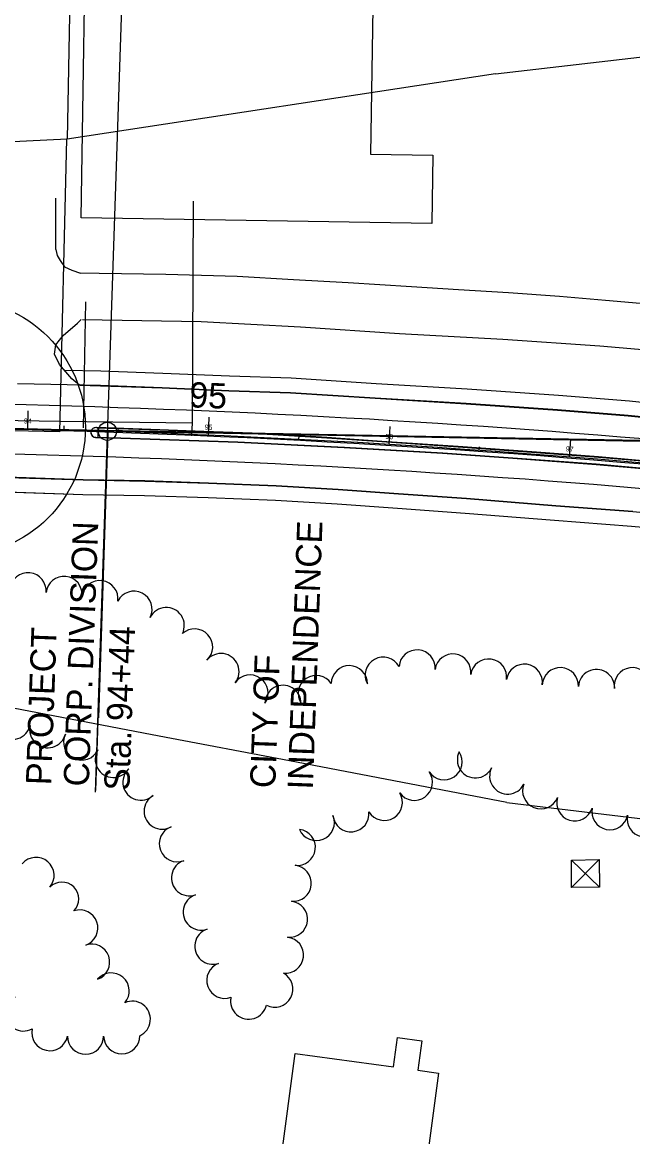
# Model space of a CAD drawing. Extents: x -25029 to 2274964, y -81170 to 687028.
# Drawn here: x -7558 to -7220, y -66444 to -65828 of the extents above; entities that cross this region are included whole.
import ezdxf

# ---------------------------------------------------------------- set-up
doc = ezdxf.new("R2010")
doc.units = 0
for name, color, linetype in [('81911BEA - RW_X_Fee_RW', 7, 'Continuous'), ('AP_X_Lights', 7, 'Continuous'), ('AP_X_Markings', 7, 'Continuous'), ('BD_X_Canopy', 7, 'Continuous'), ('BLDG', 7, 'Continuous'), ('DV_X_Corp_Line', 7, 'Continuous'), ('GE_X_CL_100', 7, 'Continuous'), ('GE_X_CL_20', 7, 'Continuous'), ('GK_Visualization', 7, 'Continuous'), ('MT_P_Edge_Line', 7, 'Continuous'), ('MT_P_Lane_Line', 7, 'Continuous'), ('PM_P_Stop_Line', 7, 'Continuous'), ('PV_X_EOP', 7, 'Continuous'), ('TRANSPWRLN', 7, 'Continuous'), ('TREES', 7, 'Continuous')]:
    doc.layers.add(name, color=color, linetype=linetype)

msp = doc.modelspace()

# ---------------------------------------------------------------- linework, layer by layer
at = {"layer": '81911BEA - RW_X_Fee_RW'}
msp.add_line((-7296.2, -65856.19), (-7533.08, -65892.28), dxfattribs=at)
for points in [[(-7296.2, -65856.19), (-7146.45, -65838.75), (-7145.25, -65838.61)], [(-7533.08, -65892.28), (-7660.66, -65898.53), (-7677.81, -65899.37)], [(-7289.97, -66259.31), (-7410.13, -66236.33), (-7482.13, -66222.56), (-7598.71, -66200.26), (-7782.14, -66167.64)], [(-7289.97, -66259.31), (-7139.67, -66277.34), (-7138.07, -66277.53)]]:
    msp.add_lwpolyline(points, dxfattribs=at)
at = {"layer": 'AP_X_Lights'}
msp.add_lwpolyline([(-7600.57, -66086.28), (-7524.38, -66088.82), (-7490.24, -66089.44), (-7455.15, -66090.65), (-7417.9, -66092.11), (-7383.77, -66094.13), (-7350.34, -66096.49), (-7312.85, -66099.14), (-7263.47, -66103.16), (-7220.94, -66106.34), (-7175.12, -66110.42), (-7125.17, -66115.15), (-7081.28, -66119.12), (-7044.93, -66123.63), (-7002.82, -66128.55), (-6956.8, -66134.1), (-6913.64, -66139.8), (-6870.76, -66146.32)], dxfattribs=at)
at = {"layer": 'AP_X_Markings'}
for p, q in [((-7464.12, -66056.51), (-7463.82, -66049.29)), ((-7510.49, -66054.77), (-7515.79, -66212.53))]:
    msp.add_line(p, q, dxfattribs=at)
at = {"layer": 'BD_X_Canopy'}
for p, q in [((-7463.82, -66049.29), (-7463.15, -65926.63)), ((-7523.97, -66052.08), (-7522.66, -65982.31)), ((-7751.13, -66045.45), (-7537.16, -66048.31)), ((-7537.16, -66048.31), (-7463.82, -66049.29)), ((-7594, -66051.77), (-7120.12, -66060.66)), ((-7534.79, -66052.88), (-7534.76, -66050.88))]:
    msp.add_line(p, q, dxfattribs=at)
msp.add_circle((-7594, -66051.77), 71.03, dxfattribs=at)
at = {"layer": 'BLDG'}
for points in [[(-7362.65, -65738.59), (-7365.24, -65900.65), (-7330.85, -65901.2), (-7331.45, -65938.87), (-7525.36, -65935.77), (-7522.16, -65736.04)], [(-7352.52, -66405.54), (-7350.36, -66389.41), (-7336.89, -66391.21), (-7339.08, -66407.55), (-7327.63, -66409.08), (-7343.54, -66528.02), (-7422.86, -66517.41), (-7406.92, -66398.26)]]:
    msp.add_lwpolyline(points, close=True, dxfattribs=at)
at = {"layer": 'DV_X_Corp_Line'}
for p, q in [((-7501.07, -65763.18), (-7517.55, -66253.54)), ((-7531.46, -65806.7), (-7533.08, -65892.28)), ((-7533.48, -65892.3), (-7537.3, -66054.17)), ((-7533.08, -65892.28), (-7533.48, -65892.3)), ((-7533.08, -65892.28), (-7533.48, -65892.3)), ((-7533.48, -65892.3), (-7533.08, -65892.28)), ((-7533.48, -65892.3), (-7533.08, -65892.28)), ((-7537.3, -66054.17), (-7737.3, -66050.39))]:
    msp.add_line(p, q, dxfattribs=at)
at = {"layer": 'GE_X_CL_100'}
for p, q in [((-7554.82, -66052.64), (-7554.57, -66042.64)), ((-7454.88, -66056.07), (-7454.45, -66046.08)), ((-7510.84, -66053.93), (-7517.46, -66252.67)), ((-7510.84, -66053.93), (-7510.84, -66053.93)), ((-7355.02, -66061.24), (-7354.41, -66051.26)), ((-7255.26, -66068.15), (-7254.48, -66058.19))]:
    msp.add_line(p, q, dxfattribs=at)
msp.add_circle((-7510.84, -66053.93), 5, dxfattribs=at)
msp.add_arc((-7701.63, -71785.78), 5735.02, 79.475877, 88.9247, dxfattribs=at)
at = {"layer": 'GE_X_CL_20'}
for p, q in [((-12238.95, -65963.84), (-7122.08, -66061.19)), ((-7554.82, -66052.64), (-7554.77, -66050.64)), ((-7504.85, -66054.13), (-7504.78, -66052.14)), ((-7454.88, -66056.07), (-7454.8, -66054.07)), ((-7404.94, -66058.44), (-7404.84, -66056.44)), ((-7355.02, -66061.24), (-7354.9, -66059.24)), ((-7305.12, -66064.48), (-7304.99, -66062.49)), ((-7255.26, -66068.15), (-7255.1, -66066.16))]:
    msp.add_line(p, q, dxfattribs=at)
msp.add_arc((-7704.96, -71780.77), 5729.63, 79.452222, 88.91, dxfattribs=at)
at = {"layer": 'GK_Visualization'}
msp.add_arc((-7701.63, -71785.78), 5735.02, 79.475877, 88.9247, dxfattribs=at)
msp.add_arc((-7701.63, -71785.78), 5735.02, 79.475877, 88.9247, dxfattribs=at)
at = {"layer": 'MT_P_Edge_Line'}
for p, q in [((-7514.65, -66028.91), (-7525.98, -66028.67)), ((-7480.51, -66030.09), (-7514.65, -66028.91)), ((-7443.6, -66031.69), (-7480.52, -66030.09)), ((-7409.6, -66032.8), (-7443.59, -66031.69)), ((-7362.71, -66035.86), (-7409.61, -66032.8)), ((-7312.44, -66038.85), (-7362.71, -66035.86)), ((-7261.91, -66042.33), (-7312.44, -66038.85)), ((-7222.85, -66045.51), (-7261.91, -66042.33)), ((-7188.08, -66048.95), (-7222.86, -66045.51)), ((-7516.74, -66051.68), (-7481.89, -66052.87)), ((-7481.88, -66052.87), (-7457.47, -66053.86)), ((-7457.48, -66053.86), (-7425.38, -66055.01)), ((-7425.37, -66055.02), (-7389.51, -66057.22)), ((-7503.41, -66057.9), (-7517.33, -66057.51)), ((-7438.71, -66060.13), (-7503.41, -66057.9)), ((-7379.78, -66063.16), (-7438.72, -66060.13)), ((-7389.51, -66057.22), (-7358.97, -66059.31)), ((-7358.97, -66059.31), (-7316.75, -66062.21)), ((-7325.39, -66066.23), (-7379.78, -66063.16)), ((-7286.6, -66068.98), (-7325.39, -66066.23)), ((-7316.75, -66062.21), (-7273.56, -66065.33)), ((-7273.56, -66065.33), (-7239.11, -66067.92)), ((-7239.1, -66067.92), (-7202.49, -66071.19)), ((-7240.41, -66072.44), (-7286.6, -66068.98)), ((-7204.86, -66075.62), (-7240.42, -66072.44)), ((-7600.34, -66078.03), (-7524.17, -66080.57)), ((-7524.17, -66080.57), (-7490.03, -66081.19)), ((-7490.03, -66081.19), (-7454.85, -66082.4)), ((-7454.84, -66082.4), (-7417.49, -66083.86)), ((-7417.49, -66083.87), (-7383.24, -66085.9)), ((-7383.24, -66085.9), (-7349.76, -66088.27)), ((-7349.76, -66088.27), (-7312.23, -66090.92)), ((-7312.22, -66090.92), (-7262.82, -66094.94)), ((-7262.83, -66094.94), (-7220.27, -66098.12))]:
    msp.add_line(p, q, dxfattribs=at)
msp.add_lwpolyline([(-7515.97, -66057.26), (-7515.88, -66051.96), (-7516.98, -66051.9), (-7517.81, -66051.95), (-7518.32, -66052.11), (-7518.79, -66052.38), (-7519.19, -66052.72), (-7519.48, -66053.09), (-7519.72, -66053.53), (-7519.85, -66053.92), (-7519.93, -66054.41), (-7519.89, -66055.03), (-7519.75, -66055.55), (-7519.48, -66056.07), (-7519.07, -66056.55), (-7518.66, -66056.86), (-7518.12, -66057.12), (-7517.54, -66057.25), (-7516.94, -66057.28), (-7516.21, -66057.3)], close=True, dxfattribs=at)
at = {"layer": 'MT_P_Lane_Line'}
for radius, start in [(5748.29, 80.845144), (5720.86, 80.84919)]:
    msp.add_arc((-7701.63, -71785.78), radius, start, 88.9247, dxfattribs=at)
at = {"layer": 'PM_P_Stop_Line'}
msp.add_line((-12236.92, -65964.61), (-7120.03, -66060.65), dxfattribs=at)
msp.add_arc((-7701.44, -71780.38), 5729.63, 79.466922, 88.9247, dxfattribs=at)
at = {"layer": 'PV_X_EOP'}
for p, q in [((-7539.35, -65953.27), (-7539.35, -65924.97)), ((-7539.35, -65953.27), (-7538.68, -65956.62)), ((-7538.68, -65956.62), (-7537.01, -65959.47)), ((-7537.01, -65959.47), (-7534.5, -65962.82)), ((-7534.5, -65962.82), (-7530.48, -65964.83)), ((-7530.48, -65964.83), (-7525.63, -65966.39)), ((-7524.63, -65992.11), (-7458.97, -65993.19)), ((-7458.97, -65993.19), (-7403.95, -65996.13)), ((-7403.95, -65996.13), (-7349.22, -65999.84)), ((-7349.22, -65999.84), (-7292.17, -66003.03)), ((-7292.17, -66003.03), (-7238.49, -66006.58)), ((-7238.49, -66006.58), (-7192.73, -66010.53)), ((-7514.42, -66020.67), (-7534.46, -66020.23)), ((-7480.19, -66021.85), (-7514.42, -66020.67)), ((-7443.28, -66023.45), (-7480.19, -66021.85)), ((-7409.2, -66024.56), (-7443.28, -66023.45)), ((-7362.2, -66027.63), (-7409.2, -66024.56)), ((-7514.64, -66028.66), (-7560.6, -66027.65)), ((-7480.5, -66029.84), (-7514.64, -66028.66)), ((-7443.58, -66031.44), (-7480.5, -66029.84)), ((-7311.91, -66030.62), (-7362.2, -66027.63)), ((-7261.3, -66034.11), (-7311.91, -66030.62)), ((-7409.59, -66032.55), (-7443.58, -66031.44)), ((-7362.69, -66035.61), (-7409.59, -66032.55)), ((-7312.42, -66038.6), (-7362.69, -66035.61)), ((-7222.12, -66037.3), (-7261.3, -66034.11)), ((-7187.24, -66040.75), (-7222.12, -66037.3)), ((-7261.89, -66042.08), (-7312.42, -66038.6)), ((-7222.83, -66045.26), (-7261.89, -66042.08)), ((-7188.05, -66048.7), (-7222.83, -66045.26)), ((-7516.75, -66051.93), (-7481.89, -66053.12)), ((-7515.97, -66057.26), (-7515.88, -66051.89)), ((-7481.89, -66053.12), (-7457.48, -66054.11)), ((-7457.48, -66054.11), (-7425.38, -66055.26)), ((-7425.38, -66055.26), (-7389.52, -66057.46)), ((-7503.4, -66057.65), (-7517.16, -66057.27)), ((-7438.7, -66059.88), (-7503.4, -66057.65)), ((-7379.76, -66062.91), (-7438.7, -66059.88)), ((-7389.52, -66057.46), (-7358.98, -66059.55)), ((-7358.98, -66059.55), (-7316.76, -66062.45)), ((-7325.37, -66065.98), (-7379.76, -66062.91)), ((-7286.58, -66068.73), (-7325.37, -66065.98)), ((-7316.76, -66062.45), (-7273.57, -66065.57)), ((-7273.57, -66065.57), (-7239.12, -66068.16)), ((-7239.12, -66068.16), (-7202.51, -66071.43)), ((-7240.39, -66072.19), (-7286.58, -66068.73)), ((-7204.83, -66075.37), (-7240.39, -66072.19)), ((-7600.34, -66078.28), (-7524.17, -66080.82)), ((-7600.57, -66086.28), (-7524.38, -66088.82)), ((-7524.17, -66080.82), (-7490.03, -66081.44)), ((-7490.03, -66081.44), (-7454.85, -66082.65)), ((-7454.85, -66082.65), (-7417.5, -66084.11)), ((-7417.5, -66084.11), (-7383.25, -66086.14)), ((-7383.25, -66086.14), (-7349.77, -66088.51)), ((-7524.38, -66088.82), (-7490.24, -66089.44)), ((-7490.24, -66089.44), (-7455.15, -66090.65)), ((-7455.15, -66090.65), (-7417.9, -66092.11)), ((-7417.9, -66092.11), (-7383.77, -66094.13)), ((-7349.77, -66088.51), (-7312.24, -66091.16)), ((-7312.24, -66091.16), (-7262.84, -66095.18)), ((-7383.77, -66094.13), (-7350.34, -66096.49)), ((-7350.34, -66096.49), (-7312.85, -66099.14)), ((-7312.85, -66099.14), (-7263.47, -66103.16)), ((-7262.84, -66095.18), (-7220.28, -66098.36)), ((-7220.28, -66098.36), (-7174.38, -66102.45)), ((-7263.47, -66103.16), (-7220.94, -66106.34)), ((-7220.94, -66106.34), (-7175.12, -66110.42))]:
    msp.add_line(p, q, dxfattribs=at)
for points in [[(-6886.57, -66020.35), (-6917.85, -66016.42), (-6947.1, -66012.74), (-6967.62, -66009.8), (-6994.36, -66006.46), (-7018.73, -66003.58), (-7049.1, -66000.02), (-7075.92, -65997.23), (-7106.93, -65993.87), (-7132.49, -65991.25), (-7156.66, -65988.79), (-7180.89, -65986.41), (-7207.65, -65983.97), (-7235.32, -65981.45), (-7260.82, -65979.25), (-7289.05, -65977.27), (-7316.53, -65975.73), (-7342.53, -65974.01), (-7377.62, -65971.75), (-7407.82, -65970.02), (-7439.07, -65968.33), (-7478.53, -65967.24), (-7515.33, -65966.63), (-7525.95, -65966.38)], [(-7526.2, -66028.4), (-7530.55, -66024.92), (-7537.35, -66016.92), (-7540.15, -66011.32), (-7539.35, -66006.12), (-7535.35, -66000.92), (-7527.35, -65994.12), (-7525.26, -65992.09)]]:
    msp.add_lwpolyline(points, dxfattribs=at)
msp.add_arc((-7517.24, -66054.58), 2.69, 79.45091, 271.74987, dxfattribs=at)
at = {"layer": 'TRANSPWRLN'}
for p, q in [((-7238.65, -66306.23), (-7254.1, -66291.18)), ((-7254.06, -66306.43), (-7238.85, -66290.83))]:
    msp.add_line(p, q, dxfattribs=at)
msp.add_lwpolyline([(-7254.06, -66306.43), (-7254.1, -66291.18), (-7238.85, -66290.83), (-7238.65, -66306.23), (-7254.06, -66306.43)], dxfattribs=at)
at = {"layer": 'TREES'}
for centre, radius, start, end in [((-7554.71, -66142.2), 10, 354.25001, 174.25001), ((-7534.81, -66144.2), 10, 354.25001, 174.25001), ((-7514.95, -66146.53), 10, 352.34581, 172.34581), ((-7496.11, -66152.37), 10, 333.22424, 153.22424), ((-7478.26, -66161.39), 10, 333.18629, 153.18629), ((-7462.58, -66173.27), 10, 312.47116, 132.47116), ((-7448, -66186.87), 10, 321.53132, 141.53132), ((-7358.27, -66188.92), 10, 28.83856, 208.83856), ((-7339.54, -66184.88), 10, 355.52716, 175.52716), ((-7319.72, -66187.08), 9.95, 351.80193, 171.80193), ((-7377.03, -66193.59), 10, 359.12321, 179.12321), ((-7299.97, -66189.92), 10, 351.80193, 171.80193), ((-7280.18, -66192.78), 10, 351.80193, 171.80193), ((-7260.29, -66194.7), 10, 357.13871, 177.13871), ((-7220.44, -66194.7), 10, 8.50764, 188.50764), ((-7431.92, -66198.75), 10, 325.56484, 145.56484), ((-7395.35, -66198.99), 10, 33.67667, 213.67667), ((-7240.31, -66195.69), 10, 357.18558, 177.18558), ((-7413.67, -66204.47), 10, 359.63057, 179.63057), ((-7563.19, -66214.33), 10, 166.21159, 346.21159), ((-7543.77, -66219.1), 10, 166.18248, 346.18248), ((-7525.07, -66225.88), 10, 153.98322, 333.98322), ((-7507.56, -66235.49), 10, 148.48611, 328.48611), ((-7324.56, -66236.82), 10, 213.58432, 33.58432), ((-7307.28, -66235.76), 10, 153.43495, 333.43495), ((-7492.27, -66248.09), 10, 132.53864, 312.53864), ((-7289.4, -66244.7), 10, 153.43495, 333.43495), ((-7341.02, -66248.18), 10, 215.64702, 35.64702), ((-7271.17, -66252.89), 10, 158.19432, 338.19432), ((-7480.55, -66264.14), 10, 119.74488, 299.74488), ((-7357.65, -66259.27), 10, 211.75117, 31.75117), ((-7252.32, -66259.51), 10, 163.09429, 343.09429), ((-7376.09, -66265.58), 10, 186.01177, 6.01177), ((-7232.95, -66264.41), 10, 168.53047, 348.53047), ((-7395.28, -66270.45), 10, 202.46403, 22.46403), ((-7213.35, -66268.39), 10, 168.53047, 348.53047), ((-7472.11, -66282.2), 10, 110.37656, 290.37656), ((-7405.76, -66284.19), 10, 262.89044, 82.89044), ((-7550.29, -66299.7), 10, 319.49623, 139.49623), ((-7465.4, -66301.04), 10, 108.80943, 288.80943), ((-7408.03, -66304.06), 10, 264.05314, 84.05314), ((-7536.02, -66312.76), 9.35, 315.43079, 135.43079), ((-7458.95, -66319.97), 10, 108.80943, 288.80943), ((-7410.11, -66323.95), 10, 264.05314, 84.05314), ((-7526.09, -66328.78), 10, 289.05771, 109.05771), ((-7452.5, -66338.9), 10, 108.80943, 288.80943), ((-7519.56, -66347.68), 10, 289.0577, 109.0577), ((-7412.32, -66343.83), 10, 263.23368, 83.23368), ((-7445.86, -66357.76), 10, 109.9756, 289.9756), ((-7508.72, -66363.66), 10, 319.23779, 139.23779), ((-7418.2, -66362.59), 10, 241.95158, 61.95158), ((-7557.18, -66375.82), 10, 117.92948, 297.92948), ((-7497.03, -66379.3), 10, 294.31577, 114.31577), ((-7432.67, -66369.29), 10, 167.73304, 347.73304), ((-7542.7, -66386.69), 10, 168.27898, 348.27898), ((-7522.91, -66388.64), 10, 180.43218, 0.43218), ((-7502.91, -66388.49), 10, 180.43846, 0.43846)]:
    msp.add_arc(centre, radius, start, end, dxfattribs=at)

# ---------------------------------------------------------------- texts
at = {"layer": 'GE_X_CL_100'}
for s, rotation, p in [('95', 357.53412, (-7465.75, -66040.59)), ('CORP. DIVISION', 87.93217, (-7521.13, -66250.67)), ('INDEPENDENCE', 87.93217, (-7397.18, -66252.34)), ('PROJECT', 87.93217, (-7541.96, -66249.92)), ('Sta. 94+44', 87.93217, (-7498.68, -66253.02)), ('CITY OF', 87.93217, (-7418, -66251.59))]:
    msp.add_text(s, height=14, rotation=rotation, dxfattribs=at).set_placement(p)
at = {"layer": 'GE_X_CL_20'}
for s, rotation, p in [('94', 358.53317, (-7557.02, -66049.58)), ('95', 357.53412, (-7457.06, -66052.97)), ('96', 356.53507, (-7357.15, -66058.11)), ('97', 355.53602, (-7257.39, -66064.98))]:
    msp.add_text(s, height=2.8, rotation=rotation, dxfattribs=at).set_placement(p)

doc.saveas('drawing.dxf')
